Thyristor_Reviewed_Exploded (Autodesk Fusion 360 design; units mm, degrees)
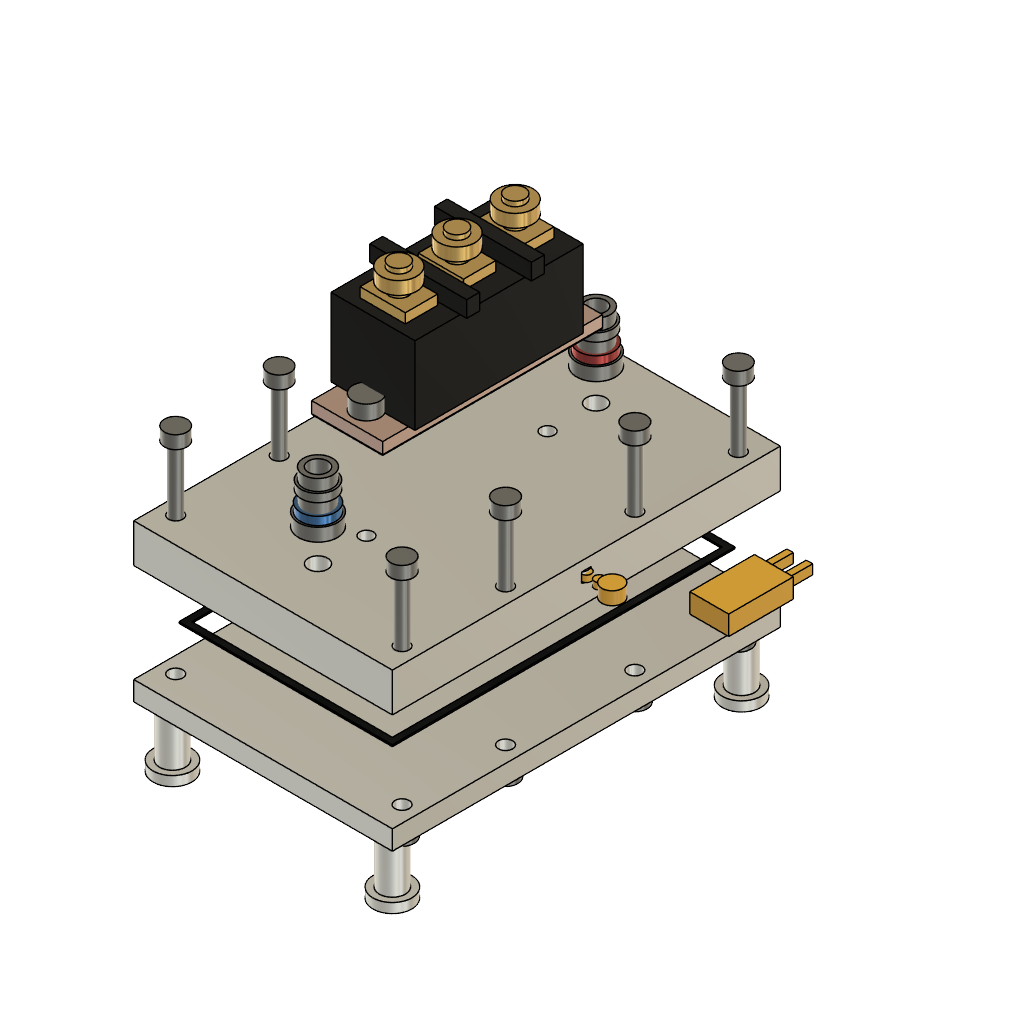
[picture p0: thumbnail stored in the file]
part number: 2026-11-02-01-28-30-721
part number: 2026-11-02-02-59-40-221
part number: 2026-11-02-02-59-43-084
part number: 2026-11-02-02-59-43-519
part number: 2026-11-02-02-59-44-128
part number: 2026-11-02-02-59-44-602
part number: 2026-11-02-02-59-44-987
part number: 2026-11-02-02-59-46-241
part number: 2026-11-02-02-59-47-034
part number: 2026-11-02-02-59-47-858
part number: 2026-11-02-02-59-48-789
part number: 2026-11-02-02-59-49-745
part number: 2026-11-02-02-59-54-096
part number: 2026-11-02-02-59-54-882
part number: 2026-11-02-02-59-56-951
part number: 2026-11-02-03-00-06-820
part number: 2026-11-02-03-00-18-161
part number: 2026-11-02-03-00-22-757
work_plane "WorkPlane1" AlongDistance 0 ExtraOffset 0
sketch "Cold plate stock sketch" plane through (0, 0, 0) normal (0, 0, 1) x axis (1, 0, 0)
  line L1 (80, 0) -> (0, 0)
  line L2 (80, 120) -> (80, 0)
  line L3 (0, 120) -> (80, 120)
  line L4 (0, 0) -> (0, 120)
extrude "Extrude1" new body sketch "Cold plate stock sketch" along normal blind 12
work_plane "WorkPlane2" AlongDistance 0 ExtraOffset 0
sketch "16 Mini-Channels | 2 x 5 x 70 mm sketch" plane through (0, 0, 0) normal (0, 0, 1) x axis (1, 0, 0)
  line L1 (14.75, 25) -> (12.75, 25)
  line L2 (14.75, 95) -> (14.75, 25)
  line L3 (12.75, 95) -> (14.75, 95)
  line L4 (12.75, 25) -> (12.75, 95)
  line L5 (18.25, 25) -> (16.25, 25)
  line L6 (18.25, 95) -> (18.25, 25)
  line L7 (16.25, 95) -> (18.25, 95)
  line L8 (16.25, 25) -> (16.25, 95)
  line L9 (21.75, 25) -> (19.75, 25)
  line L10 (21.75, 95) -> (21.75, 25)
  line L11 (19.75, 95) -> (21.75, 95)
  line L12 (19.75, 25) -> (19.75, 95)
  line L13 (25.25, 25) -> (23.25, 25)
  line L14 (25.25, 95) -> (25.25, 25)
  line L15 (23.25, 95) -> (25.25, 95)
  line L16 (23.25, 25) -> (23.25, 95)
  line L17 (28.75, 25) -> (26.75, 25)
  line L18 (28.75, 95) -> (28.75, 25)
  line L19 (26.75, 95) -> (28.75, 95)
  line L20 (26.75, 25) -> (26.75, 95)
  line L21 (32.25, 25) -> (30.25, 25)
  line L22 (32.25, 95) -> (32.25, 25)
  line L23 (30.25, 95) -> (32.25, 95)
  line L24 (30.25, 25) -> (30.25, 95)
  line L25 (35.75, 25) -> (33.75, 25)
  line L26 (35.75, 95) -> (35.75, 25)
  line L27 (33.75, 95) -> (35.75, 95)
  line L28 (33.75, 25) -> (33.75, 95)
  line L29 (39.25, 25) -> (37.25, 25)
  line L30 (39.25, 95) -> (39.25, 25)
  line L31 (37.25, 95) -> (39.25, 95)
  line L32 (37.25, 25) -> (37.25, 95)
  line L33 (42.75, 25) -> (40.75, 25)
  line L34 (42.75, 95) -> (42.75, 25)
  line L35 (40.75, 95) -> (42.75, 95)
  line L36 (40.75, 25) -> (40.75, 95)
  line L37 (46.25, 25) -> (44.25, 25)
  line L38 (46.25, 95) -> (46.25, 25)
  line L39 (44.25, 95) -> (46.25, 95)
  line L40 (44.25, 25) -> (44.25, 95)
  line L41 (49.75, 25) -> (47.75, 25)
  line L42 (49.75, 95) -> (49.75, 25)
  line L43 (47.75, 95) -> (49.75, 95)
  line L44 (47.75, 25) -> (47.75, 95)
  line L45 (53.25, 25) -> (51.25, 25)
  line L46 (53.25, 95) -> (53.25, 25)
  line L47 (51.25, 95) -> (53.25, 95)
  line L48 (51.25, 25) -> (51.25, 95)
  line L49 (56.75, 25) -> (54.75, 25)
  line L50 (56.75, 95) -> (56.75, 25)
  line L51 (54.75, 95) -> (56.75, 95)
  line L52 (54.75, 25) -> (54.75, 95)
  line L53 (60.25, 25) -> (58.25, 25)
  line L54 (60.25, 95) -> (60.25, 25)
  line L55 (58.25, 95) -> (60.25, 95)
  line L56 (58.25, 25) -> (58.25, 95)
  line L57 (63.75, 25) -> (61.75, 25)
  line L58 (63.75, 95) -> (63.75, 25)
  line L59 (61.75, 95) -> (63.75, 95)
  line L60 (61.75, 25) -> (61.75, 95)
  line L61 (67.25, 25) -> (65.25, 25)
  line L62 (67.25, 95) -> (67.25, 25)
  line L63 (65.25, 95) -> (67.25, 95)
  line L64 (65.25, 25) -> (65.25, 95)
extrude "Extrude2" cut sketch "16 Mini-Channels | 2 x 5 x 70 mm sketch" along normal blind 5
work_plane "WorkPlane3" AlongDistance 0 ExtraOffset 0
sketch "Headers sketch" plane through (0, 0, 0) normal (0, 0, 1) x axis (1, 0, 0)
  line L1 (70, 10) -> (10, 10)
  line L2 (70, 25) -> (70, 10)
  line L3 (10, 25) -> (70, 25)
  line L4 (10, 10) -> (10, 25)
  line L5 (70, 95) -> (10, 95)
  line L6 (70, 110) -> (70, 95)
  line L7 (10, 110) -> (70, 110)
  line L8 (10, 95) -> (10, 110)
extrude "Extrude3" cut sketch "Headers sketch" along normal blind 5
work_plane "WorkPlane4" AlongDistance 0 ExtraOffset 0
sketch "Boundary-layer breaks sketch" plane through (0, 0, 0) normal (0, 0, 1) x axis (1, 0, 0)
  line L1 (16.3, 42) -> (14.7, 42)
  line L2 (16.3, 44.5) -> (16.3, 42)
  line L3 (14.7, 44.5) -> (16.3, 44.5)
  line L4 (14.7, 42) -> (14.7, 44.5)
  line L5 (16.3, 68) -> (14.7, 68)
  line L6 (16.3, 70.5) -> (16.3, 68)
  line L7 (14.7, 70.5) -> (16.3, 70.5)
  line L8 (14.7, 68) -> (14.7, 70.5)
  line L9 (19.8, 52) -> (18.2, 52)
  line L10 (19.8, 54.5) -> (19.8, 52)
  line L11 (18.2, 54.5) -> (19.8, 54.5)
  line L12 (18.2, 52) -> (18.2, 54.5)
  line L13 (19.8, 78) -> (18.2, 78)
  line L14 (19.8, 80.5) -> (19.8, 78)
  line L15 (18.2, 80.5) -> (19.8, 80.5)
  line L16 (18.2, 78) -> (18.2, 80.5)
  line L17 (23.3, 42) -> (21.7, 42)
  line L18 (23.3, 44.5) -> (23.3, 42)
  line L19 (21.7, 44.5) -> (23.3, 44.5)
  line L20 (21.7, 42) -> (21.7, 44.5)
  line L21 (23.3, 68) -> (21.7, 68)
  line L22 (23.3, 70.5) -> (23.3, 68)
  line L23 (21.7, 70.5) -> (23.3, 70.5)
  line L24 (21.7, 68) -> (21.7, 70.5)
  line L25 (26.8, 52) -> (25.2, 52)
  line L26 (26.8, 54.5) -> (26.8, 52)
  line L27 (25.2, 54.5) -> (26.8, 54.5)
  line L28 (25.2, 52) -> (25.2, 54.5)
  line L29 (26.8, 78) -> (25.2, 78)
  line L30 (26.8, 80.5) -> (26.8, 78)
  line L31 (25.2, 80.5) -> (26.8, 80.5)
  line L32 (25.2, 78) -> (25.2, 80.5)
  line L33 (30.3, 42) -> (28.7, 42)
  line L34 (30.3, 44.5) -> (30.3, 42)
  line L35 (28.7, 44.5) -> (30.3, 44.5)
  line L36 (28.7, 42) -> (28.7, 44.5)
  line L37 (30.3, 68) -> (28.7, 68)
  line L38 (30.3, 70.5) -> (30.3, 68)
  line L39 (28.7, 70.5) -> (30.3, 70.5)
  line L40 (28.7, 68) -> (28.7, 70.5)
  line L41 (33.8, 52) -> (32.2, 52)
  line L42 (33.8, 54.5) -> (33.8, 52)
  line L43 (32.2, 54.5) -> (33.8, 54.5)
  line L44 (32.2, 52) -> (32.2, 54.5)
  line L45 (33.8, 78) -> (32.2, 78)
  line L46 (33.8, 80.5) -> (33.8, 78)
  line L47 (32.2, 80.5) -> (33.8, 80.5)
  line L48 (32.2, 78) -> (32.2, 80.5)
  line L49 (37.3, 42) -> (35.7, 42)
  line L50 (37.3, 44.5) -> (37.3, 42)
  line L51 (35.7, 44.5) -> (37.3, 44.5)
  line L52 (35.7, 42) -> (35.7, 44.5)
  line L53 (37.3, 68) -> (35.7, 68)
  line L54 (37.3, 70.5) -> (37.3, 68)
  line L55 (35.7, 70.5) -> (37.3, 70.5)
  line L56 (35.7, 68) -> (35.7, 70.5)
  line L57 (40.8, 52) -> (39.2, 52)
  line L58 (40.8, 54.5) -> (40.8, 52)
  line L59 (39.2, 54.5) -> (40.8, 54.5)
  line L60 (39.2, 52) -> (39.2, 54.5)
  line L61 (40.8, 78) -> (39.2, 78)
  line L62 (40.8, 80.5) -> (40.8, 78)
  line L63 (39.2, 80.5) -> (40.8, 80.5)
  line L64 (39.2, 78) -> (39.2, 80.5)
  line L65 (44.3, 42) -> (42.7, 42)
  line L66 (44.3, 44.5) -> (44.3, 42)
  line L67 (42.7, 44.5) -> (44.3, 44.5)
  line L68 (42.7, 42) -> (42.7, 44.5)
  line L69 (44.3, 68) -> (42.7, 68)
  line L70 (44.3, 70.5) -> (44.3, 68)
  line L71 (42.7, 70.5) -> (44.3, 70.5)
  line L72 (42.7, 68) -> (42.7, 70.5)
  line L73 (47.8, 52) -> (46.2, 52)
  line L74 (47.8, 54.5) -> (47.8, 52)
  line L75 (46.2, 54.5) -> (47.8, 54.5)
  line L76 (46.2, 52) -> (46.2, 54.5)
  line L77 (47.8, 78) -> (46.2, 78)
  line L78 (47.8, 80.5) -> (47.8, 78)
  line L79 (46.2, 80.5) -> (47.8, 80.5)
  line L80 (46.2, 78) -> (46.2, 80.5)
  line L81 (51.3, 42) -> (49.7, 42)
  line L82 (51.3, 44.5) -> (51.3, 42)
  line L83 (49.7, 44.5) -> (51.3, 44.5)
  line L84 (49.7, 42) -> (49.7, 44.5)
  line L85 (51.3, 68) -> (49.7, 68)
  line L86 (51.3, 70.5) -> (51.3, 68)
  line L87 (49.7, 70.5) -> (51.3, 70.5)
  line L88 (49.7, 68) -> (49.7, 70.5)
  line L89 (54.8, 52) -> (53.2, 52)
  line L90 (54.8, 54.5) -> (54.8, 52)
  line L91 (53.2, 54.5) -> (54.8, 54.5)
  line L92 (53.2, 52) -> (53.2, 54.5)
  line L93 (54.8, 78) -> (53.2, 78)
  line L94 (54.8, 80.5) -> (54.8, 78)
  line L95 (53.2, 80.5) -> (54.8, 80.5)
  line L96 (53.2, 78) -> (53.2, 80.5)
  line L97 (58.3, 42) -> (56.7, 42)
  line L98 (58.3, 44.5) -> (58.3, 42)
  line L99 (56.7, 44.5) -> (58.3, 44.5)
  line L100 (56.7, 42) -> (56.7, 44.5)
  line L101 (58.3, 68) -> (56.7, 68)
  line L102 (58.3, 70.5) -> (58.3, 68)
  line L103 (56.7, 70.5) -> (58.3, 70.5)
  line L104 (56.7, 68) -> (56.7, 70.5)
  line L105 (61.8, 52) -> (60.2, 52)
  line L106 (61.8, 54.5) -> (61.8, 52)
  line L107 (60.2, 54.5) -> (61.8, 54.5)
  line L108 (60.2, 52) -> (60.2, 54.5)
  line L109 (61.8, 78) -> (60.2, 78)
  line L110 (61.8, 80.5) -> (61.8, 78)
  line L111 (60.2, 80.5) -> (61.8, 80.5)
  line L112 (60.2, 78) -> (60.2, 80.5)
  line L113 (65.3, 42) -> (63.7, 42)
  line L114 (65.3, 44.5) -> (65.3, 42)
  line L115 (63.7, 44.5) -> (65.3, 44.5)
  line L116 (63.7, 42) -> (63.7, 44.5)
  line L117 (65.3, 68) -> (63.7, 68)
  line L118 (65.3, 70.5) -> (65.3, 68)
  line L119 (63.7, 70.5) -> (65.3, 70.5)
  line L120 (63.7, 68) -> (63.7, 70.5)
extrude "Extrude4" cut sketch "Boundary-layer breaks sketch" along normal blind 5
work_plane "WorkPlane5" AlongDistance 0 ExtraOffset 0
sketch "Gasket groove 1 sketch" plane through (0, 0, 0) normal (0, 0, 1) x axis (1, 0, 0)
  line L1 (73, 7) -> (7, 7)
  line L2 (73, 9) -> (73, 7)
  line L3 (7, 9) -> (73, 9)
  line L4 (7, 7) -> (7, 9)
extrude "Extrude5" cut sketch "Gasket groove 1 sketch" along normal blind 0.5
work_plane "WorkPlane6" AlongDistance 0 ExtraOffset 0
sketch "Gasket groove 2 sketch" plane through (0, 0, 0) normal (0, 0, 1) x axis (1, 0, 0)
  line L1 (73, 111) -> (7, 111)
  line L2 (73, 113) -> (73, 111)
  line L3 (7, 113) -> (73, 113)
  line L4 (7, 111) -> (7, 113)
extrude "Extrude6" cut sketch "Gasket groove 2 sketch" along normal blind 0.5
work_plane "WorkPlane7" AlongDistance 0 ExtraOffset 0
sketch "Gasket groove 3 sketch" plane through (0, 0, 0) normal (0, 0, 1) x axis (1, 0, 0)
  line L1 (9, 9) -> (7, 9)
  line L2 (9, 111) -> (9, 9)
  line L3 (7, 111) -> (9, 111)
  line L4 (7, 9) -> (7, 111)
extrude "Extrude7" cut sketch "Gasket groove 3 sketch" along normal blind 0.5
work_plane "WorkPlane8" AlongDistance 0 ExtraOffset 0
sketch "Gasket groove 4 sketch" plane through (0, 0, 0) normal (0, 0, 1) x axis (1, 0, 0)
  line L1 (73, 9) -> (71, 9)
  line L2 (73, 111) -> (73, 9)
  line L3 (71, 111) -> (73, 111)
  line L4 (71, 9) -> (71, 111)
extrude "Extrude8" cut sketch "Gasket groove 4 sketch" along normal blind 0.5
work_plane "WorkPlane9" AlongDistance 12 ExtraOffset 0
sketch "Fluid port through-bores sketch" plane through (0, 0, 12) normal (0, 0, 1) x axis (1, 0, 0)
  circle C1 centre (40, 17) radius 3
  circle C2 centre (40, 103) radius 3
extrude "Extrude9" cut sketch "Fluid port through-bores sketch" against normal blind 7 (magnitude of "-( 7 mm )")
work_plane "WorkPlane10" AlongDistance 12 ExtraOffset 0
sketch "Cover bolt holes sketch" plane through (0, 0, 12) normal (0, 0, 1) x axis (1, 0, 0)
  circle C1 centre (5, 8) radius 2.2
  circle C2 centre (75, 8) radius 2.2
  circle C3 centre (5, 40) radius 2.2
  circle C4 centre (75, 40) radius 2.2
  circle C5 centre (5, 80) radius 2.2
  circle C6 centre (75, 80) radius 2.2
  circle C7 centre (5, 112) radius 2.2
  circle C8 centre (75, 112) radius 2.2
extrude "Extrude10" cut sketch "Cover bolt holes sketch" against normal blind 12 (magnitude of "-( 12 mm )")
work_plane "WorkPlane11" AlongDistance 12 ExtraOffset 0
sketch "SCR M5 tapped holes sketch" plane through (0, 0, 12) normal (0, 0, 1) x axis (1, 0, 0)
  circle C1 centre (40, 32) radius 2.1
  circle C2 centre (40, 88) radius 2.1
extrude "Extrude11" cut sketch "SCR M5 tapped holes sketch" along normal blind 4
work_plane "WorkPlane12" AlongDistance 6 ExtraOffset 0
sketch "Thermowell entry boss sketch" plane through (0, 0, 6) normal (0, 0, 1) x axis (1, 0, 0)
  circle C1 centre (78, 60) radius 2.5
extrude "Extrude12" add sketch "Thermowell entry boss sketch" along normal blind 3
work_plane "WorkPlane1" AlongDistance 0 ExtraOffset 0
sketch "Gasket blank sketch" plane through (0, 0, 0) normal (0, 0, 1) x axis (1, 0, 0)
  line L1 (73, 7) -> (7, 7)
  line L2 (73, 113) -> (73, 7)
  line L3 (7, 113) -> (73, 113)
  line L4 (7, 7) -> (7, 113)
extrude "Extrude1" new body sketch "Gasket blank sketch" against normal blind 0.5 (magnitude of "-( 0.5 mm )")
work_plane "WorkPlane2" AlongDistance 0 ExtraOffset 0
sketch "Gasket fluid aperture sketch" plane through (0, 0, 0) normal (0, 0, 1) x axis (1, 0, 0)
  line L1 (71, 9) -> (9, 9)
  line L2 (71, 111) -> (71, 9)
  line L3 (9, 111) -> (71, 111)
  line L4 (9, 9) -> (9, 111)
extrude "Extrude2" cut sketch "Gasket fluid aperture sketch" against normal blind 0.5 (magnitude of "-( 0.5 mm )")
work_plane "WorkPlane1" AlongDistance -0.5 ExtraOffset 0
sketch "Bottom cover slab sketch" plane through (0, 0, -0.5) normal (0, 0, 1) x axis (1, 0, 0)
  line L1 (80, 0) -> (0, 0)
  line L2 (80, 120) -> (80, 0)
  line L3 (0, 120) -> (80, 120)
  line L4 (0, 0) -> (0, 120)
extrude "Extrude1" new body sketch "Bottom cover slab sketch" against normal blind 6 (magnitude of "-( 6.0 mm )")
work_plane "WorkPlane2" AlongDistance -0.5 ExtraOffset 0
sketch "Cover bolt holes sketch" plane through (0, 0, -0.5) normal (0, 0, 1) x axis (1, 0, 0)
  circle C1 centre (5, 8) radius 2.2
  circle C2 centre (75, 8) radius 2.2
  circle C3 centre (5, 40) radius 2.2
  circle C4 centre (75, 40) radius 2.2
  circle C5 centre (5, 80) radius 2.2
  circle C6 centre (75, 80) radius 2.2
  circle C7 centre (5, 112) radius 2.2
  circle C8 centre (75, 112) radius 2.2
extrude "Extrude2" cut sketch "Cover bolt holes sketch" against normal blind 6 (magnitude of "-( 6.0 mm )")
work_plane "WorkPlane1" AlongDistance 12 ExtraOffset 0
sketch "Hex collar sketch" plane through (0, 0, 12) normal (0, 0, 1) x axis (1, 0, 0)
  circle C1 centre (40, 17) radius 6
extrude "Extrude1" new body sketch "Hex collar sketch" along normal blind 4
work_plane "WorkPlane2" AlongDistance 16 ExtraOffset 0
sketch "Barb stem sketch" plane through (0, 0, 16) normal (0, 0, 1) x axis (1, 0, 0)
  circle C1 centre (40, 17) radius 4.5
extrude "Extrude2" add sketch "Barb stem sketch" along normal blind 12
work_plane "WorkPlane3" AlongDistance 22 ExtraOffset 0
sketch "Retention barb bead sketch" plane through (0, 0, 22) normal (0, 0, 1) x axis (1, 0, 0)
  circle C1 centre (40, 17) radius 5.2
extrude "Extrude3" add sketch "Retention barb bead sketch" along normal blind 2.5
work_plane "WorkPlane4" AlongDistance 28 ExtraOffset 0
sketch "Continuous fluid bore sketch" plane through (0, 0, 28) normal (0, 0, 1) x axis (1, 0, 0)
  circle C1 centre (40, 17) radius 3
extrude "Extrude4" cut sketch "Continuous fluid bore sketch" against normal blind 16 (magnitude of "-( 16.0 mm )")
work_plane "WorkPlane1" AlongDistance 16 ExtraOffset 0
sketch "Identifier ring sketch" plane through (0, 0, 16) normal (0, 0, 1) x axis (1, 0, 0)
  circle C1 centre (40, 17) radius 5.4
extrude "Extrude1" new body sketch "Identifier ring sketch" along normal blind 2.5
work_plane "WorkPlane2" AlongDistance 16 ExtraOffset 0
sketch "Ring bore sketch" plane through (0, 0, 16) normal (0, 0, 1) x axis (1, 0, 0)
  circle C1 centre (40, 17) radius 4.5
extrude "Extrude5" cut sketch "Ring bore sketch" along normal blind 2.5
work_plane "WorkPlane1" AlongDistance 12 ExtraOffset 0
sketch "Hex collar sketch" plane through (0, 0, 12) normal (0, 0, 1) x axis (1, 0, 0)
  circle C1 centre (40, 103) radius 6
extrude "Extrude1" new body sketch "Hex collar sketch" along normal blind 4
work_plane "WorkPlane2" AlongDistance 16 ExtraOffset 0
sketch "Barb stem sketch" plane through (0, 0, 16) normal (0, 0, 1) x axis (1, 0, 0)
  circle C1 centre (40, 103) radius 4.5
extrude "Extrude2" add sketch "Barb stem sketch" along normal blind 12
work_plane "WorkPlane3" AlongDistance 22 ExtraOffset 0
sketch "Retention barb bead sketch" plane through (0, 0, 22) normal (0, 0, 1) x axis (1, 0, 0)
  circle C1 centre (40, 103) radius 5.2
extrude "Extrude3" add sketch "Retention barb bead sketch" along normal blind 2.5
work_plane "WorkPlane4" AlongDistance 28 ExtraOffset 0
sketch "Continuous fluid bore sketch" plane through (0, 0, 28) normal (0, 0, 1) x axis (1, 0, 0)
  circle C1 centre (40, 103) radius 3
extrude "Extrude4" cut sketch "Continuous fluid bore sketch" against normal blind 16 (magnitude of "-( 16.0 mm )")
work_plane "WorkPlane1" AlongDistance 16 ExtraOffset 0
sketch "Identifier ring sketch" plane through (0, 0, 16) normal (0, 0, 1) x axis (1, 0, 0)
  circle C1 centre (40, 103) radius 5.4
extrude "Extrude1" new body sketch "Identifier ring sketch" along normal blind 2.5
work_plane "WorkPlane2" AlongDistance 16 ExtraOffset 0
sketch "Ring bore sketch" plane through (0, 0, 16) normal (0, 0, 1) x axis (1, 0, 0)
  circle C1 centre (40, 103) radius 4.5
extrude "Extrude5" cut sketch "Ring bore sketch" along normal blind 2.5
work_plane "WorkPlane1" AlongDistance 12 ExtraOffset 0
sketch "TIM envelope sketch" plane through (0, 0, 12) normal (0, 0, 1) x axis (1, 0, 0)
  line L1 (51, 26) -> (29, 26)
  line L2 (51, 94) -> (51, 26)
  line L3 (29, 94) -> (51, 94)
  line L4 (29, 26) -> (29, 94)
extrude "Extrude1" new body sketch "TIM envelope sketch" along normal blind 0.2
work_plane "WorkPlane2" AlongDistance 12 ExtraOffset 0
sketch "TIM bolt clearance sketch" plane through (0, 0, 12) normal (0, 0, 1) x axis (1, 0, 0)
  circle C1 centre (40, 32) radius 2.5
  circle C2 centre (40, 88) radius 2.5
extrude "Extrude2" cut sketch "TIM bolt clearance sketch" along normal blind 0.2
work_plane "WorkPlane1" AlongDistance 12.2 ExtraOffset 0
sketch "Copper baseplate sketch" plane through (0, 0, 12.2) normal (0, 0, 1) x axis (1, 0, 0)
  line L1 (51, 26) -> (29, 26)
  line L2 (51, 94) -> (51, 26)
  line L3 (29, 94) -> (51, 94)
  line L4 (29, 26) -> (29, 94)
extrude "Extrude1" new body sketch "Copper baseplate sketch" along normal blind 3.5
work_plane "WorkPlane2" AlongDistance 12.2 ExtraOffset 0
sketch "U-bolt mounting slots sketch" plane through (0, 0, 12.2) normal (0, 0, 1) x axis (1, 0, 0)
  circle C1 centre (40, 32) radius 2.6
  circle C2 centre (40, 88) radius 2.6
extrude "Extrude2" cut sketch "U-bolt mounting slots sketch" along normal blind 3.5
work_plane "WorkPlane1" AlongDistance 15.7 ExtraOffset 0
sketch "SCR plastic body sketch" plane through (0, 0, 15.7) normal (0, 0, 1) x axis (1, 0, 0)
  line L1 (53, 34) -> (27, 34)
  line L2 (53, 86) -> (53, 34)
  line L3 (27, 86) -> (53, 86)
  line L4 (27, 34) -> (27, 86)
extrude "Extrude1" new body sketch "SCR plastic body sketch" along normal blind 24
work_plane "WorkPlane2" AlongDistance 39.7 ExtraOffset 0
sketch "Phase isolation barriers sketch" plane through (0, 0, 39.7) normal (0, 0, 1) x axis (1, 0, 0)
  line L1 (55, 48) -> (25, 48)
  line L2 (55, 52) -> (55, 48)
  line L3 (25, 52) -> (55, 52)
  line L4 (25, 48) -> (25, 52)
  line L5 (55, 68) -> (25, 68)
  line L6 (55, 72) -> (55, 68)
  line L7 (25, 72) -> (55, 72)
  line L8 (25, 68) -> (25, 72)
extrude "Extrude2" add sketch "Phase isolation barriers sketch" along normal blind 5
work_plane "WorkPlane1" AlongDistance 39.7 ExtraOffset 0
sketch "Pad_42.0 sketch" plane through (0, 0, 39.7) normal (0, 0, 1) x axis (1, 0, 0)
  line L1 (47, 37) -> (33, 37)
  line L2 (47, 47) -> (47, 37)
  line L3 (33, 47) -> (47, 47)
  line L4 (33, 37) -> (33, 47)
extrude "Extrude1" new body sketch "Pad_42.0 sketch" along normal blind 3
work_plane "WorkPlane2" AlongDistance 42.7 ExtraOffset 0
sketch "Stud_42.0 sketch" plane through (0, 0, 42.7) normal (0, 0, 1) x axis (1, 0, 0)
  circle C1 centre (40, 42) radius 3
extrude "Extrude2" add sketch "Stud_42.0 sketch" along normal blind 8
work_plane "WorkPlane3" AlongDistance 45.2 ExtraOffset 0
sketch "Nut_42.0 sketch" plane through (0, 0, 45.2) normal (0, 0, 1) x axis (1, 0, 0)
  circle C1 centre (40, 42) radius 5.5
extrude "Extrude3" add sketch "Nut_42.0 sketch" along normal blind 4
work_plane "WorkPlane4" AlongDistance 39.7 ExtraOffset 0
sketch "Pad_60.0 sketch" plane through (0, 0, 39.7) normal (0, 0, 1) x axis (1, 0, 0)
  line L1 (47, 55) -> (33, 55)
  line L2 (47, 65) -> (47, 55)
  line L3 (33, 65) -> (47, 65)
  line L4 (33, 55) -> (33, 65)
extrude "Extrude4" new body sketch "Pad_60.0 sketch" along normal blind 3
work_plane "WorkPlane5" AlongDistance 42.7 ExtraOffset 0
sketch "Stud_60.0 sketch" plane through (0, 0, 42.7) normal (0, 0, 1) x axis (1, 0, 0)
  circle C1 centre (40, 60) radius 3
extrude "Extrude5" add sketch "Stud_60.0 sketch" along normal blind 8
work_plane "WorkPlane6" AlongDistance 45.2 ExtraOffset 0
sketch "Nut_60.0 sketch" plane through (0, 0, 45.2) normal (0, 0, 1) x axis (1, 0, 0)
  circle C1 centre (40, 60) radius 5.5
extrude "Extrude6" add sketch "Nut_60.0 sketch" along normal blind 4
work_plane "WorkPlane7" AlongDistance 39.7 ExtraOffset 0
sketch "Pad_78.0 sketch" plane through (0, 0, 39.7) normal (0, 0, 1) x axis (1, 0, 0)
  line L1 (47, 73) -> (33, 73)
  line L2 (47, 83) -> (47, 73)
  line L3 (33, 83) -> (47, 83)
  line L4 (33, 73) -> (33, 83)
extrude "Extrude7" new body sketch "Pad_78.0 sketch" along normal blind 3
work_plane "WorkPlane8" AlongDistance 42.7 ExtraOffset 0
sketch "Stud_78.0 sketch" plane through (0, 0, 42.7) normal (0, 0, 1) x axis (1, 0, 0)
  circle C1 centre (40, 78) radius 3
extrude "Extrude8" add sketch "Stud_78.0 sketch" along normal blind 8
work_plane "WorkPlane9" AlongDistance 45.2 ExtraOffset 0
sketch "Nut_78.0 sketch" plane through (0, 0, 45.2) normal (0, 0, 1) x axis (1, 0, 0)
  circle C1 centre (40, 78) radius 5.5
extrude "Extrude9" add sketch "Nut_78.0 sketch" along normal blind 4
work_plane "WorkPlane1" AlongDistance 26 ExtraOffset 0
sketch "Gate pins sketch" plane through (0, 0, 26) normal (0, 0, 1) x axis (1, 0, 0)
  line L1 (27.5, 56) -> (26, 56)
  line L2 (27.5, 58.5) -> (27.5, 56)
  line L3 (26, 58.5) -> (27.5, 58.5)
  line L4 (26, 56) -> (26, 58.5)
  line L5 (27.5, 61.5) -> (26, 61.5)
  line L6 (27.5, 64) -> (27.5, 61.5)
  line L7 (26, 64) -> (27.5, 64)
  line L8 (26, 61.5) -> (26, 64)
extrude "Extrude1" new body sketch "Gate pins sketch" along normal blind 6
work_plane "WorkPlane1" AlongDistance 15.7 ExtraOffset 0
sketch "Head_32.0 sketch" plane through (0, 0, 15.7) normal (0, 0, 1) x axis (1, 0, 0)
  circle C1 centre (40, 32) radius 4.2
extrude "Extrude1" new body sketch "Head_32.0 sketch" along normal blind 4.5
work_plane "WorkPlane2" AlongDistance 15.7 ExtraOffset 0
sketch "Shank_32.0 sketch" plane through (0, 0, 15.7) normal (0, 0, 1) x axis (1, 0, 0)
  circle C1 centre (40, 32) radius 2.4
extrude "Extrude2" add sketch "Shank_32.0 sketch" against normal blind 7
work_plane "WorkPlane3" AlongDistance 15.7 ExtraOffset 0
sketch "Head_88.0 sketch" plane through (0, 0, 15.7) normal (0, 0, 1) x axis (1, 0, 0)
  circle C1 centre (40, 88) radius 4.2
extrude "Extrude3" new body sketch "Head_88.0 sketch" along normal blind 4.5
work_plane "WorkPlane4" AlongDistance 15.7 ExtraOffset 0
sketch "Shank_88.0 sketch" plane through (0, 0, 15.7) normal (0, 0, 1) x axis (1, 0, 0)
  circle C1 centre (40, 88) radius 2.4
extrude "Extrude4" add sketch "Shank_88.0 sketch" against normal blind 7
work_plane "WorkPlane1" AlongDistance 12 ExtraOffset 0
sketch "BHead_5_8 sketch" plane through (0, 0, 12) normal (0, 0, 1) x axis (1, 0, 0)
  circle C1 centre (5, 8) radius 3.5
extrude "Extrude1" new body sketch "BHead_5_8 sketch" along normal blind 4
work_plane "WorkPlane2" AlongDistance 12 ExtraOffset 0
sketch "BShank_5_8 sketch" plane through (0, 0, 12) normal (0, 0, 1) x axis (1, 0, 0)
  circle C1 centre (5, 8) radius 1.9
extrude "Extrude2" add sketch "BShank_5_8 sketch" against normal blind 22
work_plane "WorkPlane3" AlongDistance 12 ExtraOffset 0
sketch "BHead_75_8 sketch" plane through (0, 0, 12) normal (0, 0, 1) x axis (1, 0, 0)
  circle C1 centre (75, 8) radius 3.5
extrude "Extrude3" new body sketch "BHead_75_8 sketch" along normal blind 4
work_plane "WorkPlane4" AlongDistance 12 ExtraOffset 0
sketch "BShank_75_8 sketch" plane through (0, 0, 12) normal (0, 0, 1) x axis (1, 0, 0)
  circle C1 centre (75, 8) radius 1.9
extrude "Extrude4" add sketch "BShank_75_8 sketch" against normal blind 22
work_plane "WorkPlane5" AlongDistance 12 ExtraOffset 0
sketch "BHead_5_40 sketch" plane through (0, 0, 12) normal (0, 0, 1) x axis (1, 0, 0)
  circle C1 centre (5, 40) radius 3.5
extrude "Extrude5" new body sketch "BHead_5_40 sketch" along normal blind 4
work_plane "WorkPlane6" AlongDistance 12 ExtraOffset 0
sketch "BShank_5_40 sketch" plane through (0, 0, 12) normal (0, 0, 1) x axis (1, 0, 0)
  circle C1 centre (5, 40) radius 1.9
extrude "Extrude6" add sketch "BShank_5_40 sketch" against normal blind 22
work_plane "WorkPlane7" AlongDistance 12 ExtraOffset 0
sketch "BHead_75_40 sketch" plane through (0, 0, 12) normal (0, 0, 1) x axis (1, 0, 0)
  circle C1 centre (75, 40) radius 3.5
extrude "Extrude7" new body sketch "BHead_75_40 sketch" along normal blind 4
work_plane "WorkPlane8" AlongDistance 12 ExtraOffset 0
sketch "BShank_75_40 sketch" plane through (0, 0, 12) normal (0, 0, 1) x axis (1, 0, 0)
  circle C1 centre (75, 40) radius 1.9
extrude "Extrude8" add sketch "BShank_75_40 sketch" against normal blind 22
work_plane "WorkPlane9" AlongDistance 12 ExtraOffset 0
sketch "BHead_5_80 sketch" plane through (0, 0, 12) normal (0, 0, 1) x axis (1, 0, 0)
  circle C1 centre (5, 80) radius 3.5
extrude "Extrude9" new body sketch "BHead_5_80 sketch" along normal blind 4
work_plane "WorkPlane10" AlongDistance 12 ExtraOffset 0
sketch "BShank_5_80 sketch" plane through (0, 0, 12) normal (0, 0, 1) x axis (1, 0, 0)
  circle C1 centre (5, 80) radius 1.9
extrude "Extrude10" add sketch "BShank_5_80 sketch" against normal blind 22
work_plane "WorkPlane11" AlongDistance 12 ExtraOffset 0
sketch "BHead_75_80 sketch" plane through (0, 0, 12) normal (0, 0, 1) x axis (1, 0, 0)
  circle C1 centre (75, 80) radius 3.5
extrude "Extrude11" new body sketch "BHead_75_80 sketch" along normal blind 4
work_plane "WorkPlane12" AlongDistance 12 ExtraOffset 0
sketch "BShank_75_80 sketch" plane through (0, 0, 12) normal (0, 0, 1) x axis (1, 0, 0)
  circle C1 centre (75, 80) radius 1.9
extrude "Extrude12" add sketch "BShank_75_80 sketch" against normal blind 22
work_plane "WorkPlane13" AlongDistance 12 ExtraOffset 0
sketch "BHead_5_112 sketch" plane through (0, 0, 12) normal (0, 0, 1) x axis (1, 0, 0)
  circle C1 centre (5, 112) radius 3.5
extrude "Extrude13" new body sketch "BHead_5_112 sketch" along normal blind 4
work_plane "WorkPlane14" AlongDistance 12 ExtraOffset 0
sketch "BShank_5_112 sketch" plane through (0, 0, 12) normal (0, 0, 1) x axis (1, 0, 0)
  circle C1 centre (5, 112) radius 1.9
extrude "Extrude14" add sketch "BShank_5_112 sketch" against normal blind 22
work_plane "WorkPlane15" AlongDistance 12 ExtraOffset 0
sketch "BHead_75_112 sketch" plane through (0, 0, 12) normal (0, 0, 1) x axis (1, 0, 0)
  circle C1 centre (75, 112) radius 3.5
extrude "Extrude15" new body sketch "BHead_75_112 sketch" along normal blind 4
work_plane "WorkPlane16" AlongDistance 12 ExtraOffset 0
sketch "BShank_75_112 sketch" plane through (0, 0, 12) normal (0, 0, 1) x axis (1, 0, 0)
  circle C1 centre (75, 112) radius 1.9
extrude "Extrude16" add sketch "BShank_75_112 sketch" against normal blind 22
work_plane "WorkPlane1" AlongDistance -6.5 ExtraOffset 0
sketch "Nut_5_8 sketch" plane through (0, 0, -6.5) normal (0, 0, 1) x axis (1, 0, 0)
  circle C1 centre (5, 8) radius 3.8
extrude "Extrude1" new body sketch "Nut_5_8 sketch" against normal blind 3 (magnitude of "-( 3.0 mm )")
work_plane "WorkPlane2" AlongDistance -6.5 ExtraOffset 0
sketch "NutBore_5_8 sketch" plane through (0, 0, -6.5) normal (0, 0, 1) x axis (1, 0, 0)
  circle C1 centre (5, 8) radius 2
extrude "Extrude2" cut sketch "NutBore_5_8 sketch" against normal blind 3 (magnitude of "-( 3.0 mm )")
work_plane "WorkPlane3" AlongDistance -6.5 ExtraOffset 0
sketch "Nut_75_8 sketch" plane through (0, 0, -6.5) normal (0, 0, 1) x axis (1, 0, 0)
  circle C1 centre (75, 8) radius 3.8
extrude "Extrude3" new body sketch "Nut_75_8 sketch" against normal blind 3 (magnitude of "-( 3.0 mm )")
work_plane "WorkPlane4" AlongDistance -6.5 ExtraOffset 0
sketch "NutBore_75_8 sketch" plane through (0, 0, -6.5) normal (0, 0, 1) x axis (1, 0, 0)
  circle C1 centre (75, 8) radius 2
extrude "Extrude4" cut sketch "NutBore_75_8 sketch" against normal blind 3 (magnitude of "-( 3.0 mm )")
work_plane "WorkPlane5" AlongDistance -6.5 ExtraOffset 0
sketch "Nut_5_40 sketch" plane through (0, 0, -6.5) normal (0, 0, 1) x axis (1, 0, 0)
  circle C1 centre (5, 40) radius 3.8
extrude "Extrude5" new body sketch "Nut_5_40 sketch" against normal blind 3 (magnitude of "-( 3.0 mm )")
work_plane "WorkPlane6" AlongDistance -6.5 ExtraOffset 0
sketch "NutBore_5_40 sketch" plane through (0, 0, -6.5) normal (0, 0, 1) x axis (1, 0, 0)
  circle C1 centre (5, 40) radius 2
extrude "Extrude6" cut sketch "NutBore_5_40 sketch" against normal blind 3 (magnitude of "-( 3.0 mm )")
work_plane "WorkPlane7" AlongDistance -6.5 ExtraOffset 0
sketch "Nut_75_40 sketch" plane through (0, 0, -6.5) normal (0, 0, 1) x axis (1, 0, 0)
  circle C1 centre (75, 40) radius 3.8
extrude "Extrude7" new body sketch "Nut_75_40 sketch" against normal blind 3 (magnitude of "-( 3.0 mm )")
work_plane "WorkPlane8" AlongDistance -6.5 ExtraOffset 0
sketch "NutBore_75_40 sketch" plane through (0, 0, -6.5) normal (0, 0, 1) x axis (1, 0, 0)
  circle C1 centre (75, 40) radius 2
extrude "Extrude8" cut sketch "NutBore_75_40 sketch" against normal blind 3 (magnitude of "-( 3.0 mm )")
work_plane "WorkPlane9" AlongDistance -6.5 ExtraOffset 0
sketch "Nut_5_80 sketch" plane through (0, 0, -6.5) normal (0, 0, 1) x axis (1, 0, 0)
  circle C1 centre (5, 80) radius 3.8
extrude "Extrude9" new body sketch "Nut_5_80 sketch" against normal blind 3 (magnitude of "-( 3.0 mm )")
work_plane "WorkPlane10" AlongDistance -6.5 ExtraOffset 0
sketch "NutBore_5_80 sketch" plane through (0, 0, -6.5) normal (0, 0, 1) x axis (1, 0, 0)
  circle C1 centre (5, 80) radius 2
extrude "Extrude10" cut sketch "NutBore_5_80 sketch" against normal blind 3 (magnitude of "-( 3.0 mm )")
work_plane "WorkPlane11" AlongDistance -6.5 ExtraOffset 0
sketch "Nut_75_80 sketch" plane through (0, 0, -6.5) normal (0, 0, 1) x axis (1, 0, 0)
  circle C1 centre (75, 80) radius 3.8
extrude "Extrude11" new body sketch "Nut_75_80 sketch" against normal blind 3 (magnitude of "-( 3.0 mm )")
work_plane "WorkPlane12" AlongDistance -6.5 ExtraOffset 0
sketch "NutBore_75_80 sketch" plane through (0, 0, -6.5) normal (0, 0, 1) x axis (1, 0, 0)
  circle C1 centre (75, 80) radius 2
extrude "Extrude12" cut sketch "NutBore_75_80 sketch" against normal blind 3 (magnitude of "-( 3.0 mm )")
work_plane "WorkPlane13" AlongDistance -6.5 ExtraOffset 0
sketch "Nut_5_112 sketch" plane through (0, 0, -6.5) normal (0, 0, 1) x axis (1, 0, 0)
  circle C1 centre (5, 112) radius 3.8
extrude "Extrude13" new body sketch "Nut_5_112 sketch" against normal blind 3 (magnitude of "-( 3.0 mm )")
work_plane "WorkPlane14" AlongDistance -6.5 ExtraOffset 0
sketch "NutBore_5_112 sketch" plane through (0, 0, -6.5) normal (0, 0, 1) x axis (1, 0, 0)
  circle C1 centre (5, 112) radius 2
extrude "Extrude14" cut sketch "NutBore_5_112 sketch" against normal blind 3 (magnitude of "-( 3.0 mm )")
work_plane "WorkPlane15" AlongDistance -6.5 ExtraOffset 0
sketch "Nut_75_112 sketch" plane through (0, 0, -6.5) normal (0, 0, 1) x axis (1, 0, 0)
  circle C1 centre (75, 112) radius 3.8
extrude "Extrude15" new body sketch "Nut_75_112 sketch" against normal blind 3 (magnitude of "-( 3.0 mm )")
work_plane "WorkPlane16" AlongDistance -6.5 ExtraOffset 0
sketch "NutBore_75_112 sketch" plane through (0, 0, -6.5) normal (0, 0, 1) x axis (1, 0, 0)
  circle C1 centre (75, 112) radius 2
extrude "Extrude16" cut sketch "NutBore_75_112 sketch" against normal blind 3 (magnitude of "-( 3.0 mm )")
work_plane "WorkPlane1" AlongDistance 6.5 ExtraOffset 0
sketch "Sensor probe in thermowell sketch" plane through (0, 0, 6.5) normal (0, 0, 1) x axis (1, 0, 0)
  circle C1 centre (80, 60) radius 1.5
extrude "Extrude1" new body sketch "Sensor probe in thermowell sketch" along normal blind 2
work_plane "WorkPlane2" AlongDistance 6.5 ExtraOffset 0
sketch "Probe sheath sketch" plane through (0, 0, 6.5) normal (0, 0, 1) x axis (1, 0, 0)
  circle C1 centre (84, 60) radius 1.5
extrude "Extrude2" new body sketch "Probe sheath sketch" along normal blind 2
work_plane "WorkPlane3" AlongDistance 5.5 ExtraOffset 0
sketch "Brass compression gland sketch" plane through (0, 0, 5.5) normal (0, 0, 1) x axis (1, 0, 0)
  circle C1 centre (88, 60) radius 3.2
extrude "Extrude3" add sketch "Brass compression gland sketch" along normal blind 4
work_plane "WorkPlane4" AlongDistance 3 ExtraOffset 0
sketch "Yellow connector plug sketch" plane through (0, 0, 3) normal (0, 0, 1) x axis (1, 0, 0)
  line L1 (114, 70) -> (102, 70)
  line L2 (114, 90) -> (114, 70)
  line L3 (102, 90) -> (114, 90)
  line L4 (102, 70) -> (102, 90)
extrude "Extrude4" new body sketch "Yellow connector plug sketch" along normal blind 6
work_plane "WorkPlane5" AlongDistance 4.5 ExtraOffset 0
sketch "Spade prongs sketch" plane through (0, 0, 4.5) normal (0, 0, 1) x axis (1, 0, 0)
  line L1 (106, 90) -> (104, 90)
  line L2 (106, 98) -> (106, 90)
  line L3 (104, 98) -> (106, 98)
  line L4 (104, 90) -> (104, 98)
  line L5 (112, 90) -> (110, 90)
  line L6 (112, 98) -> (112, 90)
  line L7 (110, 98) -> (112, 98)
  line L8 (110, 90) -> (110, 98)
extrude "Extrude5" add sketch "Spade prongs sketch" along normal blind 3
work_plane "WorkPlane1" AlongDistance -6.5 ExtraOffset 0
sketch "Leg_6_6 sketch" plane through (0, 0, -6.5) normal (0, 0, 1) x axis (1, 0, 0)
  circle C1 centre (6, 6) radius 4
extrude "Extrude1" new body sketch "Leg_6_6 sketch" against normal blind 16 (magnitude of "-( 16.0 mm )")
work_plane "WorkPlane2" AlongDistance -22.5 ExtraOffset 0
sketch "Foot_6_6 sketch" plane through (0, 0, -22.5) normal (0, 0, 1) x axis (1, 0, 0)
  circle C1 centre (6, 6) radius 6
extrude "Extrude2" add sketch "Foot_6_6 sketch" against normal blind 3 (magnitude of "-( 3.0 mm )")
work_plane "WorkPlane3" AlongDistance -6.5 ExtraOffset 0
sketch "Leg_74_6 sketch" plane through (0, 0, -6.5) normal (0, 0, 1) x axis (1, 0, 0)
  circle C1 centre (74, 6) radius 4
extrude "Extrude3" new body sketch "Leg_74_6 sketch" against normal blind 16 (magnitude of "-( 16.0 mm )")
work_plane "WorkPlane4" AlongDistance -22.5 ExtraOffset 0
sketch "Foot_74_6 sketch" plane through (0, 0, -22.5) normal (0, 0, 1) x axis (1, 0, 0)
  circle C1 centre (74, 6) radius 6
extrude "Extrude4" add sketch "Foot_74_6 sketch" against normal blind 3 (magnitude of "-( 3.0 mm )")
work_plane "WorkPlane5" AlongDistance -6.5 ExtraOffset 0
sketch "Leg_6_114 sketch" plane through (0, 0, -6.5) normal (0, 0, 1) x axis (1, 0, 0)
  circle C1 centre (6, 114) radius 4
extrude "Extrude5" new body sketch "Leg_6_114 sketch" against normal blind 16 (magnitude of "-( 16.0 mm )")
work_plane "WorkPlane6" AlongDistance -22.5 ExtraOffset 0
sketch "Foot_6_114 sketch" plane through (0, 0, -22.5) normal (0, 0, 1) x axis (1, 0, 0)
  circle C1 centre (6, 114) radius 6
extrude "Extrude6" add sketch "Foot_6_114 sketch" against normal blind 3 (magnitude of "-( 3.0 mm )")
work_plane "WorkPlane7" AlongDistance -6.5 ExtraOffset 0
sketch "Leg_74_114 sketch" plane through (0, 0, -6.5) normal (0, 0, 1) x axis (1, 0, 0)
  circle C1 centre (74, 114) radius 4
extrude "Extrude7" new body sketch "Leg_74_114 sketch" against normal blind 16 (magnitude of "-( 16.0 mm )")
work_plane "WorkPlane8" AlongDistance -22.5 ExtraOffset 0
sketch "Foot_74_114 sketch" plane through (0, 0, -22.5) normal (0, 0, 1) x axis (1, 0, 0)
  circle C1 centre (74, 114) radius 6
extrude "Extrude8" add sketch "Foot_74_114 sketch" against normal blind 3 (magnitude of "-( 3.0 mm )")
position "Position1"
work_plane "WorkPlane13" AlongDistance 12 ExtraOffset 0
sketch "Sketch13" plane through (0, 0, 12) normal (0, 0, 1) x axis (1, 0, 0)
  circle C1 centre (40, 32) radius 2.1
  circle C2 centre (40, 88) radius 2.1
extrude "Extrude13" cut sketch "Sketch13" against normal blind 4 (magnitude of "-( 4.00 mm )")
position "Position2"
position "Position3"
position "Position4"
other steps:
create_component "CreateComponent23"
create_component "CreateComponent24"
create_component "CreateComponent25"
create_component "CreateComponent26"
create_component "CreateComponent27"
extrude "Extrude2" cut sketch "Ring bore sketch" along normal blind 2.5
create_component "CreateComponent28"
create_component "CreateComponent29"
extrude "Extrude2" cut sketch "Ring bore sketch" along normal blind 2.5
create_component "CreateComponent30"
create_component "CreateComponent31"
create_component "CreateComponent32"
create_component "CreateComponent33"
create_component "CreateComponent34"
create_component "CreateComponent35"
create_component "CreateComponent36"
create_component "CreateComponent37"
create_component "CreateComponent38"
create_component "CreateComponent39"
